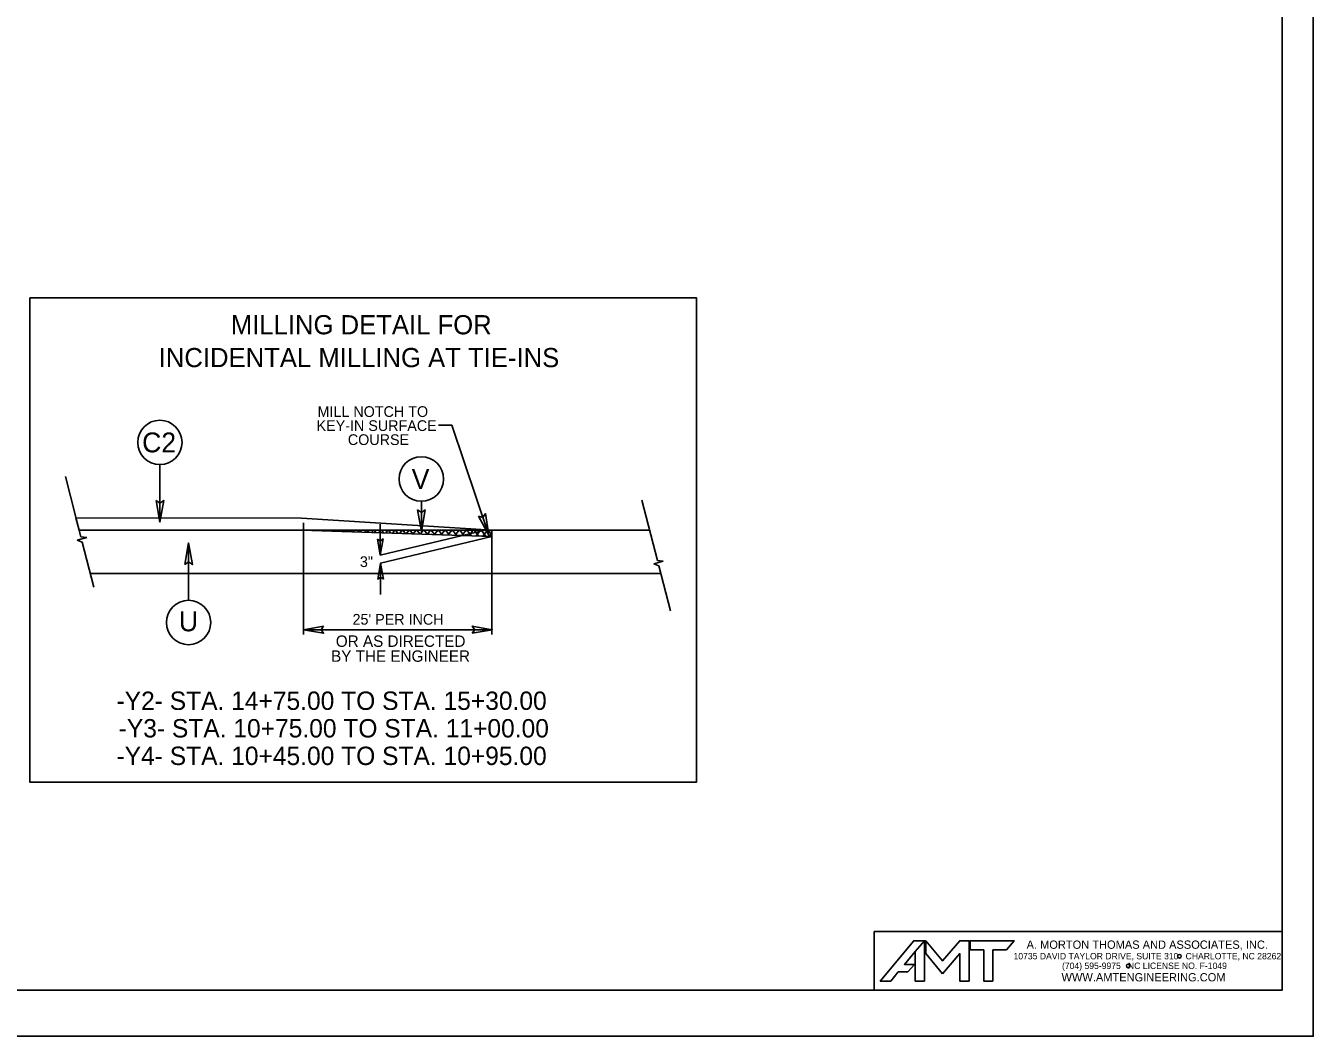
# Model space of a CAD drawing. Extents: x 1487909 to 1489267, y 497866 to 499814.
# Drawn here: x 1488981.6 to 1489051.7, y 498348 to 498403 of the extents above; entities that cross this region are included whole.
import ezdxf

# ---------------------------------------------------------------- set-up
doc = ezdxf.new("R2010")
doc.units = 0
for name, color, linetype in [('Default', 7, 'Continuous'), ('Prop Grid Mask', 7, 'Continuous'), ('Prop Shade Medium', 7, 'Continuous'), ('Sheet Block Title CELL', 7, 'Continuous'), ('Sheet Plot Border Outside CELL', 7, 'Continuous'), ('Sheet Typical CELL', 7, 'Continuous'), ('Typical ID Circle CELL', 7, 'Continuous'), ('Typical Pavement Slope CELL', 7, 'Continuous'), ('Typical Terminator CELL', 7, 'Continuous'), ('Typical Text ID Circle CELL', 7, 'Continuous'), ('Typical Text Label CELL', 7, 'Continuous')]:
    doc.layers.add(name, color=color, linetype=linetype)

msp = doc.modelspace()

# ---------------------------------------------------------------- linework, layer by layer
at = {"layer": 'Default'}
for p, q in [((1489004.775, 498381.221), (1489004.046, 498381.221)), ((1489004.775, 498381.221), (1489006.789, 498375.219)), ((1488983.744, 498378.424), (1488984.594, 498375.134)), ((1489015.118, 498377.137), (1489015.967, 498373.846)), ((1488996.385, 498375.945), (1488996.385, 498375.945)), ((1488996.702, 498375.896), (1488996.702, 498369.815)), ((1488984.593, 498375.134), (1488984.907, 498375.094)), ((1488984.907, 498375.497), (1489015.557, 498375.497)), ((1488997.023, 498375.497), (1488997.012, 498375.484)), ((1488997.412, 498375.497), (1488997.391, 498375.471)), ((1488997.469, 498375.468), (1488997.446, 498375.497)), ((1488997.8, 498375.497), (1488997.768, 498375.458)), ((1488997.873, 498375.455), (1488997.839, 498375.497)), ((1488998.189, 498375.497), (1488998.147, 498375.445)), ((1488998.273, 498375.441), (1488998.227, 498375.497)), ((1488998.577, 498375.497), (1488998.525, 498375.432)), ((1488998.671, 498375.427), (1488998.615, 498375.497)), ((1488998.966, 498375.497), (1488998.904, 498375.42)), ((1488999.069, 498375.414), (1488999.003, 498375.497)), ((1488999.353, 498375.497), (1488999.281, 498375.407)), ((1488999.469, 498375.4), (1488999.391, 498375.497)), ((1488999.741, 498375.497), (1488999.658, 498375.394)), ((1488999.867, 498375.387), (1488999.779, 498375.497)), ((1489000.129, 498375.497), (1489000.036, 498375.381)), ((1489000.267, 498375.373), (1489000.167, 498375.497)), ((1489000.517, 498375.497), (1489000.414, 498375.368)), ((1489000.665, 498375.359), (1489000.555, 498375.497)), ((1489000.905, 498375.497), (1489000.791, 498375.355)), ((1489000.88, 498375.821), (1489000.88, 498374.143)), ((1489006.583, 498375.497), (1489000.88, 498374.143)), ((1489006.959, 498375.145), (1489000.902, 498373.707)), ((1489001.064, 498375.346), (1489000.943, 498375.497)), ((1489001.292, 498375.497), (1489001.169, 498375.342)), ((1489001.463, 498375.332), (1489001.331, 498375.497)), ((1489001.68, 498375.497), (1489001.546, 498375.329)), ((1489001.861, 498375.319), (1489001.719, 498375.497)), ((1489002.068, 498375.497), (1489001.924, 498375.317)), ((1489002.26, 498375.305), (1489002.106, 498375.497)), ((1489002.456, 498375.497), (1489002.301, 498375.304)), ((1489002.659, 498375.291), (1489002.494, 498375.497)), ((1489002.844, 498375.497), (1489002.679, 498375.291)), ((1489003.058, 498375.278), (1489002.882, 498375.497)), ((1489003.232, 498375.497), (1489003.056, 498375.278)), ((1489003.456, 498375.264), (1489003.27, 498375.497)), ((1489003.62, 498375.497), (1489003.434, 498375.265)), ((1489003.855, 498375.251), (1489003.658, 498375.497)), ((1489004.008, 498375.497), (1489003.811, 498375.252)), ((1489004.254, 498375.237), (1489004.046, 498375.497)), ((1489004.396, 498375.497), (1489004.189, 498375.239)), ((1489004.653, 498375.223), (1489004.433, 498375.497)), ((1489004.783, 498375.497), (1489004.567, 498375.226)), ((1489005.051, 498375.21), (1489004.822, 498375.497)), ((1489005.171, 498375.497), (1489004.944, 498375.214)), ((1489005.45, 498375.196), (1489005.209, 498375.497)), ((1489005.56, 498375.497), (1489005.322, 498375.201)), ((1489005.849, 498375.183), (1489005.597, 498375.497)), ((1489005.947, 498375.497), (1489005.699, 498375.188)), ((1489006.248, 498375.169), (1489005.985, 498375.497)), ((1489006.335, 498375.497), (1489006.077, 498375.175)), ((1489006.647, 498375.156), (1489006.373, 498375.497)), ((1489006.723, 498375.497), (1489006.455, 498375.162)), ((1489006.96, 498375.249), (1489006.761, 498375.497)), ((1489006.96, 498375.308), (1489006.832, 498375.149)), ((1489006.96, 498371.496), (1489006.96, 498375.497)), ((1488984.907, 498375.094), (1488984.39, 498374.956)), ((1488984.39, 498374.956), (1488984.666, 498374.853)), ((1488984.666, 498374.853), (1488985.3, 498372.398)), ((1489006.936, 498374.794), (1489006.936, 498374.794)), ((1489016.281, 498373.807), (1489015.764, 498373.669)), ((1489015.967, 498373.846), (1489016.281, 498373.807)), ((1489016.148, 498373.145), (1488985.107, 498373.145)), ((1489000.903, 498371.999), (1489000.902, 498373.707)), ((1489006.96, 498373.046), (1489006.96, 498369.815)), ((1489015.764, 498373.669), (1489016.039, 498373.565)), ((1489016.039, 498373.565), (1489016.673, 498371.111)), ((1489006.98, 498370.081), (1488996.702, 498370.081))]:
    msp.add_line(p, q, dxfattribs=at)
for points in [[(1489000.73, 498375.014), (1489000.88, 498374.143), (1489001.035, 498375.019), (1489000.88, 498374.908)], [(1489001.052, 498372.836), (1489000.902, 498373.707), (1489000.748, 498372.831), (1489000.902, 498372.942)], [(1488997.791, 498370.268), (1488996.702, 498370.081), (1488997.797, 498369.887), (1488997.658, 498370.081)], [(1489005.891, 498369.893), (1489006.98, 498370.081), (1489005.885, 498370.274), (1489006.024, 498370.081)]]:
    msp.add_lwpolyline(points, close=True, dxfattribs=at)
at = {"layer": 'Prop Grid Mask'}
msp.add_lwpolyline([(1489027.76, 498353.648), (1489049.964, 498353.648), (1489049.964, 498350.453), (1489027.76, 498350.453)], close=True, dxfattribs=at)
at = {"layer": 'Prop Shade Medium'}
msp.add_lwpolyline([(1489006.96, 498375.497), (1488996.604, 498376.155), (1488984.314, 498376.169), (1488984.5, 498375.497), (1488984.907, 498375.497)], close=True, dxfattribs=at)
at = {"layer": 'Sheet Block Title CELL'}
msp.add_lwpolyline([(1489027.76, 498353.648), (1489049.964, 498353.648), (1489049.964, 498350.453), (1489027.76, 498350.453)], close=True, dxfattribs=at)
for points in [[(1489030.002, 498352.562), (1489030.506, 498353.152), (1489029.918, 498353.152), (1489028.095, 498350.957), (1489028.665, 498350.957), (1489029.074, 498351.45), (1489029.596, 498351.45), (1489029.954, 498351.865), (1489029.414, 498351.865), (1489030.002, 498352.562)], [(1489030.506, 498350.957), (1489030.506, 498353.152), (1489030.002, 498352.562), (1489030.002, 498350.957), (1489030.506, 498350.957)], [(1489031.493, 498351.344), (1489032.425, 498352.455), (1489032.425, 498350.957), (1489032.929, 498350.957), (1489032.929, 498353.152), (1489032.425, 498353.152), (1489031.493, 498352.057), (1489030.571, 498353.152), (1489030.571, 498352.453), (1489031.493, 498351.344)], [(1489034.232, 498350.957), (1489034.232, 498352.649), (1489034.961, 498352.649), (1489035.382, 498353.152), (1489032.993, 498353.152), (1489032.993, 498352.649), (1489033.729, 498352.649), (1489033.729, 498350.957), (1489034.232, 498350.957)]]:
    msp.add_lwpolyline(points, dxfattribs=at)
for centre in [(1489044.382, 498352.305), (1489041.591, 498351.782)]:
    msp.add_circle(centre, 0.1, dxfattribs=at)
at = {"layer": 'Sheet Plot Border Outside CELL'}
msp.add_lwpolyline([(1489051.664, 498457.953), (1488883.264, 498457.953), (1488883.264, 498347.953), (1489051.664, 498347.953)], close=True, dxfattribs=at)
at = {"layer": 'Sheet Typical CELL'}
for points in [[(1489049.964, 498455.453), (1488899.964, 498455.453), (1488899.964, 498350.453), (1489049.964, 498350.453)], [(1488981.815, 498388.152), (1489018.093, 498388.152), (1489018.093, 498361.776), (1488981.815, 498361.776)]]:
    msp.add_lwpolyline(points, close=True, dxfattribs=at)
at = {"layer": 'Typical ID Circle CELL'}
for p, q in [((1488988.887, 498379.064), (1488988.887, 498375.941)), ((1489003.12, 498377.073), (1489003.12, 498375.426)), ((1489003.12, 498377.073), (1489003.12, 498375.426)), ((1488990.45, 498371.681), (1488990.45, 498374.804))]:
    msp.add_line(p, q, dxfattribs=at)
for centre in [(1488988.887, 498380.273), (1489003.119, 498378.282), (1489003.119, 498378.282), (1488990.45, 498370.472)]:
    msp.add_circle(centre, 1.208, dxfattribs=at)
at = {"layer": 'Typical Pavement Slope CELL'}
for p, q in [((1488984.314, 498376.169), (1488996.604, 498376.155)), ((1488996.604, 498376.155), (1489006.96, 498375.497)), ((1489006.96, 498375.145), (1488996.619, 498375.497)), ((1489006.959, 498374.792), (1489006.96, 498375.497))]:
    msp.add_line(p, q, dxfattribs=at)
at = {"layer": 'Typical Terminator CELL'}
for points in [[(1488988.686, 498377.113), (1488988.887, 498375.941), (1488989.096, 498377.119), (1488988.887, 498376.969)], [(1488988.686, 498377.113), (1488988.887, 498375.941), (1488989.096, 498377.119), (1488988.887, 498376.969)], [(1488988.686, 498377.113), (1488988.887, 498375.941), (1488989.096, 498377.119), (1488988.887, 498376.969)], [(1489002.918, 498376.597), (1489003.12, 498375.426), (1489003.328, 498376.604), (1489003.12, 498376.454)], [(1489006.225, 498376.265), (1489006.789, 498375.219), (1489006.612, 498376.402), (1489006.462, 498376.194)], [(1488990.248, 498373.632), (1488990.45, 498374.804), (1488990.658, 498373.626), (1488990.45, 498373.775)]]:
    msp.add_lwpolyline(points, close=True, dxfattribs=at)

# ---------------------------------------------------------------- texts
at = {"layer": 'Default'}
for s, height, rotation, p in [('MILLING DETAIL FOR', 1.04413, 359.99993, (1488992.749, 498386.158)), ('MILL NOTCH TO', 0.58284, 0.00001, (1488997.468, 498381.661)), ('KEY-IN SURFACE', 0.58284, 0.00001, (1488997.417, 498380.897)), ('COURSE', 0.5828, 0.00001, (1488999.118, 498380.133)), ('3"  ', 0.5828, 359.99952, (1488999.774, 498373.491)), ("25' PER INCH", 0.58284, 359.99993, (1488999.373, 498370.353)), ('OR AS DIRECTED', 0.62057, 359.99993, (1488998.465, 498369.147)), ('BY THE ENGINEER', 0.62057, 359.99993, (1488998.206, 498368.334))]:
    msp.add_text(s, height=height, rotation=rotation, dxfattribs=at).set_placement(p)
at = {"layer": 'Sheet Block Title CELL'}
for s, height, p in [('A. MORTON THOMAS AND ASSOCIATES, INC.', 0.45, (1489036.061, 498352.713)), ('10735 DAVID TAYLOR DRIVE, SUITE 310   CHARLOTTE, NC 28262', 0.35, (1489035.351, 498352.138)), ('WWW.AMTENGINEERING.COM', 0.45, (1489037.963, 498350.938)), ('(704) 595-9975   NC LICENSE NO. F-1049', 0.35, (1489037.989, 498351.613))]:
    msp.add_text(s, height=height, rotation=359.99952, dxfattribs=at).set_placement(p)
at = {"layer": 'Typical Text ID Circle CELL'}
for s, height, p in [('C2', 1.0817, (1488987.922, 498379.732)), ('V', 1.082, (1489002.593, 498377.741)), ('U', 1.082, (1488989.922, 498369.994))]:
    msp.add_text(s, height=height, dxfattribs=at).set_placement(p)
at = {"layer": 'Typical Text Label CELL'}
msp.add_text('INCIDENTAL MILLING AT TIE-INS', height=1.04413, rotation=360, dxfattribs=at).set_placement((1488988.824, 498384.37))
for s, p in [('-Y2- STA. 14+75.00 TO STA. 15+30.00', (1488986.527, 498365.715)), ('-Y3- STA. 10+75.00 TO STA. 11+00.00', (1488986.646, 498364.215)), ('-Y4- STA. 10+45.00 TO STA. 10+95.00', (1488986.527, 498362.715))]:
    msp.add_text(s, height=1, dxfattribs=at).set_placement(p)

doc.saveas('drawing.dxf')
